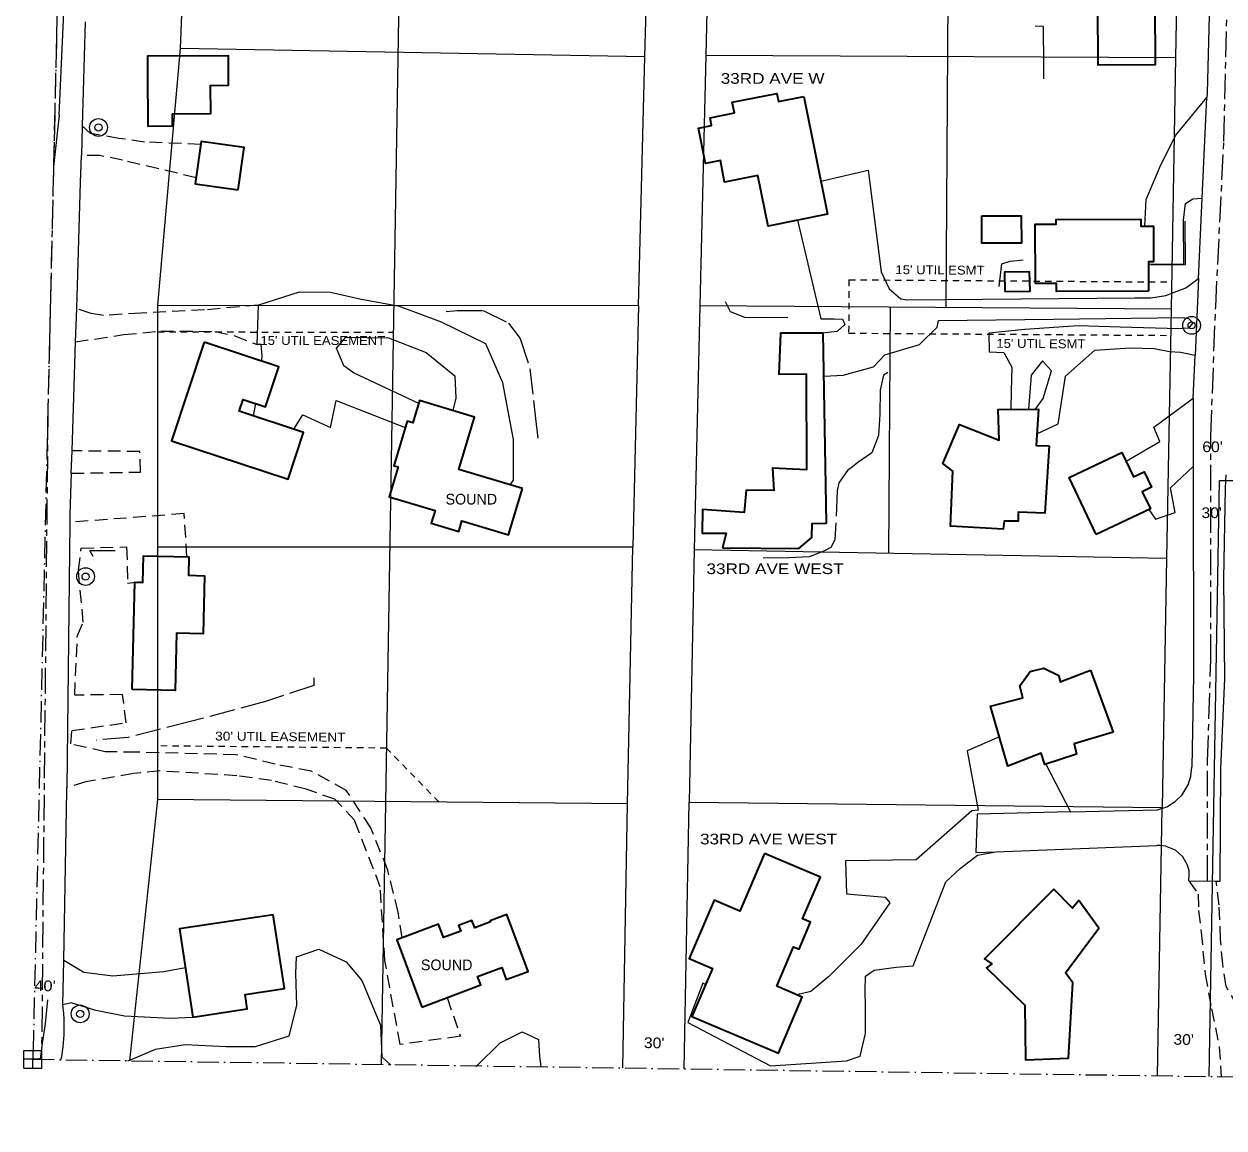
# Model space of a CAD drawing. Extents: x -861682 to -858969, y -1797841 to -1795153.
# Drawn here: x -861682 to -861008, y -1797836 to -1797216 of the extents above; entities that cross this region are included whole.
import ezdxf

# ---------------------------------------------------------------- set-up
doc = ezdxf.new("R2010")
doc.units = 0
doc.header["$LTSCALE"] = 2.4
for name, pattern in [('DOT_DASHED', [7.7, 5, -1.2, 0.3, -1.2]), ('LONG_DASH_SHORT_DASH', [9.9, 6, -1.2, 1.5, -1.2]), ('LONG_DASHED', [7.5, 6, -1.5]), ('MEDIUM_DASHED', [4.5, 3, -1.5]), ('SHORT_DASHED', [2.7, 1.5, -1.2])]:
    doc.linetypes.add(name, pattern=pattern)
for name, color, linetype, lineweight in [('10', 7, 'Continuous', 25), ('11', 7, 'Continuous', 13), ('12', 7, 'Continuous', 35), ('14', 7, 'Continuous', 25), ('18', 7, 'Continuous', 13), ('30', 7, 'Continuous', 13), ('31', 7, 'Continuous', 13), ('32', 7, 'LONG_DASH_SHORT_DASH', 13), ('42', 7, 'Continuous', 25), ('46', 7, 'Continuous', 13), ('47', 7, 'SHORT_DASHED', 13), ('52', 7, 'LONG_DASHED', 13), ('54', 7, 'Continuous', 13), ('61', 7, 'Continuous', 13)]:
    doc.layers.add(name, color=color, linetype=linetype, lineweight=lineweight)
doc.layers.add('43', color=7, linetype='Continuous')

msp = doc.modelspace()

# ---------------------------------------------------------------- linework, layer by layer
at = {"layer": '10'}
for p, q in [((-861647.407, -1797214.598), (-861649.011, -1797273.028)), ((-861019.853, -1797313.609), (-861017.272, -1797257.025)), ((-861649.011, -1797273.028), (-861649.47, -1797289.752)), ((-861021.917, -1797358.836), (-861019.853, -1797313.609)), ((-861021.917, -1797358.836), (-861023.882, -1797401.894)), ((-861024.977, -1797425.893), (-861023.882, -1797401.894)), ((-861024.977, -1797425.893), (-861024.938, -1797464.393)), ((-861655.169, -1797468.153), (-861654.723, -1797455.579)), ((-861656.037, -1797495.755), (-861657.707, -1797644.754)), ((-861093.92, -1797658.395), (-861045.067, -1797657.174)), ((-861135.81, -1797680.763), (-861045.459, -1797677.249)), ((-861027.43, -1797697.014), (-861012.076, -1797697.157)), ((-861659.839, -1797766.63), (-861659.402, -1797741.788))]:
    msp.add_line(p, q, dxfattribs=at)
for points in [[(-861015.76, -1797203.66), (-861017.164, -1797254.647), (-861017.272, -1797257.025)], [(-861652.099, -1797375.675), (-861649.886, -1797304.898), (-861649.47, -1797289.752)], [(-861654.723, -1797455.579), (-861653.654, -1797425.356), (-861652.684, -1797394.362), (-861652.099, -1797375.675)], [(-861024.938, -1797464.393), (-861024.823, -1797581.757), (-861025.797, -1797633.244)], [(-861655.169, -1797468.153), (-861655.987, -1797491.254), (-861656.037, -1797495.755)], [(-861012.076, -1797697.157), (-861009.718, -1797697.179), (-861009.5, -1797633.887), (-861007.105, -1797583.339), (-861007.802, -1797527.372), (-861006.825, -1797476.594), (-861006.515, -1797469.019)], [(-861045.067, -1797657.174), (-861039.847, -1797655.447), (-861035.151, -1797652.587), (-861031.221, -1797648.742), (-861027.798, -1797643.108), (-861026.266, -1797638.213), (-861025.841, -1797634.937), (-861025.797, -1797633.244)], [(-861659.402, -1797741.788), (-861657.726, -1797646.418), (-861657.707, -1797644.754)], [(-861093.92, -1797658.395), (-861146.371, -1797659.706), (-861146.994, -1797681.199), (-861135.81, -1797680.763)], [(-861027.43, -1797697.014), (-861027.137, -1797693.726), (-861027.304, -1797691.53), (-861028.091, -1797688.324), (-861030.741, -1797683.522), (-861034.803, -1797679.835), (-861040.484, -1797677.515), (-861043.767, -1797677.172), (-861045.459, -1797677.249)], [(-861660.946, -1797797.525), (-861660.54, -1797795.669), (-861659.753, -1797790.216), (-861659.211, -1797783.628), (-861659.093, -1797779.222), (-861659.094, -1797778.12), (-861659.172, -1797774.815), (-861659.352, -1797771.606), (-861659.839, -1797766.63)]]:
    msp.add_lwpolyline(points, dxfattribs=at)
at = {"layer": '11'}
for p, q in [((-861550.805, -1797395.896), (-861549.949, -1797373.692)), ((-861551.74, -1797428.996), (-861552.921, -1797435.919)), ((-861107.715, -1797631.519), (-861093.92, -1797658.395))]:
    msp.add_line(p, q, dxfattribs=at)
for points in [[(-861052.021, -1797329.413), (-861051.404, -1797314.296), (-861043.216, -1797294.898), (-861034.781, -1797278.334), (-861017.272, -1797257.025)], [(-861234.103, -1797304.022), (-861207.574, -1797297.92), (-861200.26, -1797355.041), (-861195.735, -1797364.47), (-861189.1, -1797370.111), (-861185.791, -1797370.806), (-861057.794, -1797369.583), (-861048.82, -1797369.547), (-861040.323, -1797368.332), (-861029.005, -1797364.036), (-861021.917, -1797358.836)], [(-861050.072, -1797350.658), (-861030.239, -1797350.58), (-861030.338, -1797326.02), (-861029.196, -1797316.569), (-861025.191, -1797313.955), (-861019.853, -1797313.609)], [(-861247.232, -1797325.95), (-861234.163, -1797381.392), (-861226.606, -1797381.362), (-861221.881, -1797381.579), (-861220.688, -1797384.645), (-861224.924, -1797388.44), (-861233.405, -1797389.416)], [(-861408.546, -1797474.711), (-861406.676, -1797472.07), (-861406.767, -1797449.162), (-861412.799, -1797417.305), (-861422.333, -1797395.38), (-861447.179, -1797383.198), (-861470.83, -1797374.555), (-861493.046, -1797370.393), (-861509.592, -1797366.681), (-861527.069, -1797366.514), (-861549.949, -1797373.692)], [(-861232.292, -1797413.694), (-861221.519, -1797412.988), (-861204.534, -1797408.432), (-861198.185, -1797401.557), (-861178.606, -1797395.811), (-861168.726, -1797386.089), (-861168.033, -1797382.307), (-861103.326, -1797381.574), (-861030.591, -1797380.573), (-861027.518, -1797381.269), (-861025.147, -1797383.621), (-861027.497, -1797386.701), (-861032.927, -1797386.959), (-861065.994, -1797386.147), (-861089.614, -1797385.298), (-861119.598, -1797387.307), (-861139.663, -1797389.513), (-861139.622, -1797399.904), (-861131.354, -1797400.344), (-861126.834, -1797408.591), (-861127.254, -1797421.818), (-861127.337, -1797432.208)], [(-861459.978, -1797428.941), (-861496.659, -1797411.736), (-861502.107, -1797407.744), (-861506.161, -1797397.841), (-861500.991, -1797391.68), (-861476.9, -1797392.056), (-861455.849, -1797400.237), (-861439.737, -1797413.398), (-861439.215, -1797425.912), (-861440.747, -1797432.94)], [(-861548.133, -1797405.261), (-861547.945, -1797402.259), (-861548.442, -1797395.885), (-861550.805, -1797395.896)], [(-861112.775, -1797446.049), (-861100.729, -1797440.369), (-861096.585, -1797413.665), (-861080.113, -1797398.957), (-861060.279, -1797397.696), (-861046.816, -1797398.114), (-861038.308, -1797399.733), (-861032.166, -1797400.181), (-861023.882, -1797401.894)], [(-861113.564, -1797432.153), (-861109.287, -1797426.233), (-861104.627, -1797410.628), (-861109.609, -1797404.98), (-861115.953, -1797413.035), (-861117.386, -1797432.168)], [(-861530.196, -1797443.392), (-861525.141, -1797435.231), (-861509.525, -1797442.489), (-861506.279, -1797427.362), (-861467.509, -1797442.49)], [(-861062.691, -1797461.316), (-861043.773, -1797450.293), (-861047.111, -1797442.277), (-861024.977, -1797425.893)], [(-861049.855, -1797488.55), (-861046.195, -1797493.993), (-861035.111, -1797490.17), (-861037.764, -1797476.247), (-861024.938, -1797464.393)], [(-861133.806, -1797616.207), (-861151.946, -1797624.068), (-861145.673, -1797657.342), (-861149.213, -1797657.828), (-861180.512, -1797685.348), (-861220.186, -1797685.743), (-861219.639, -1797704.398), (-861197.905, -1797706.2), (-861195.294, -1797709.496), (-861211.496, -1797732.705), (-861229.608, -1797750.726), (-861239.729, -1797759.268), (-861247.679, -1797761.044)], [(-861298.827, -1797755.228), (-861300.442, -1797754.552), (-861308.856, -1797776.549), (-861262.47, -1797800.924), (-861219.735, -1797798.154), (-861211.952, -1797795.526), (-861208.933, -1797782.761), (-861208.995, -1797767.41), (-861209.265, -1797758.91), (-861209.062, -1797750.643), (-861204.116, -1797747.317), (-861191.842, -1797745.615), (-861182.163, -1797744.867), (-861163.932, -1797697.562), (-861155.932, -1797690.209), (-861146.043, -1797682.612), (-861135.81, -1797680.763)], [(-861591.03, -1797745.96), (-861603.235, -1797748.22), (-861631.801, -1797750.696), (-861648.105, -1797748.636), (-861659.402, -1797741.788)], [(-861586.784, -1797773.884), (-861599.588, -1797774.419), (-861625.335, -1797773.105), (-861641.407, -1797769.863), (-861655.121, -1797765.667), (-861659.839, -1797766.63)]]:
    msp.add_lwpolyline(points, dxfattribs=at)
at = {"layer": '11', "linetype": 'MEDIUM_DASHED'}
for points in [[(-861582.445, -1797283.493), (-861614.08, -1797282.082), (-861628.339, -1797280.061), (-861644.329, -1797277.245), (-861649.011, -1797273.028)], [(-861585.041, -1797302.194), (-861626.32, -1797292.287), (-861639.083, -1797289.74), (-861649.47, -1797289.752)], [(-861549.949, -1797373.692), (-861580.403, -1797376.412), (-861615.821, -1797378.208), (-861637.07, -1797379.474), (-861643.923, -1797378.32), (-861652.099, -1797375.675)], [(-861652.684, -1797394.362), (-861625.691, -1797390.292), (-861604.917, -1797388.319), (-861574.451, -1797388.433), (-861563.341, -1797390.987), (-861550.805, -1797395.896)], [(-861655.169, -1797468.153), (-861616.171, -1797467.479), (-861616.69, -1797455.909), (-861654.723, -1797455.579)], [(-861590.157, -1797515.049), (-861591.753, -1797490.76), (-861656.037, -1797495.755)], [(-861469.362, -1797729.004), (-861471.589, -1797714.627), (-861477.352, -1797691.035), (-861486.895, -1797667.221), (-861500.677, -1797646.259), (-861520.322, -1797635.474), (-861540.648, -1797631.542), (-861562.633, -1797626.198), (-861618.61, -1797624.77), (-861636.087, -1797624.605), (-861655.47, -1797620.196), (-861654.792, -1797612.636), (-861624.344, -1797608.263), (-861626.297, -1797592.448), (-861653.218, -1797592.792), (-861651.7, -1797559.251), (-861648.424, -1797551.681), (-861651.138, -1797522.644), (-861649.535, -1797510.121), (-861624.032, -1797509.547), (-861623.478, -1797529.854), (-861614.948, -1797528.693)], [(-861444.026, -1797762.632), (-861436.592, -1797784.388), (-861470.345, -1797789.01), (-861479.037, -1797741.815), (-861481.566, -1797700.499), (-861495.886, -1797663.244), (-861507.034, -1797651.245), (-861523.115, -1797645.641), (-861542.736, -1797640.76), (-861562.113, -1797638.004), (-861605.342, -1797635.344), (-861620.215, -1797636.821), (-861646.883, -1797641.415), (-861657.707, -1797644.754)], [(-861027.43, -1797697.014), (-861022.205, -1797704.55), (-861021.932, -1797713.759), (-861020.467, -1797725.798), (-861018.247, -1797749.405), (-861014.626, -1797768.992), (-861010.29, -1797790.229), (-861009.146, -1797807.296)], [(-860793.836, -1797741.71), (-860796.661, -1797765.758), (-860796.654, -1797767.411), (-860810.281, -1797785.178), (-860824.892, -1797792.794), (-860842.836, -1797793.81), (-860860.091, -1797790.1), (-860902.834, -1797790.507), (-860938.496, -1797790.178), (-860966.606, -1797788.637), (-860988.843, -1797779.28), (-860999.752, -1797767.752), (-861006.41, -1797756.442), (-861008.35, -1797743.934), (-861009.588, -1797729.769), (-861010.373, -1797710.643), (-861012.076, -1797697.157)]]:
    msp.add_lwpolyline(points, dxfattribs=at)
at = {"layer": '12'}
for points in [[(-861078.528, -1797205.062), (-861046.411, -1797204.933), (-861046.275, -1797238.704), (-861078.392, -1797238.834)], [(-861612.348, -1797242.635), (-861612.226, -1797273.099), (-861598.292, -1797273.043), (-861598.32, -1797266.195), (-861576.829, -1797266.107), (-861576.894, -1797250.286), (-861566.738, -1797250.244), (-861566.806, -1797233.714), (-861612.384, -1797233.902)], [(-861243.636, -1797256.499), (-861230.383, -1797322.571), (-861263.762, -1797329.266), (-861269.47, -1797300.809), (-861288.134, -1797304.553), (-861290.55, -1797292.511), (-861298.907, -1797294.188), (-861302.894, -1797274.319), (-861295.468, -1797272.829), (-861296.33, -1797268.533), (-861282.629, -1797265.784), (-861283.832, -1797259.789), (-861258.786, -1797254.763), (-861257.864, -1797259.356)], [(-861561.307, -1797309.029), (-861557.983, -1797285.077), (-861582.199, -1797281.717), (-861585.523, -1797305.669)], [(-861143.706, -1797323.641), (-861121.508, -1797323.552), (-861121.446, -1797338.902), (-861143.644, -1797338.992)], [(-861050.016, -1797365.773), (-861101.735, -1797365.98), (-861101.753, -1797361.493), (-861113.561, -1797361.54), (-861113.694, -1797328.242), (-861101.886, -1797328.195), (-861101.896, -1797325.597), (-861054.429, -1797325.414), (-861054.414, -1797329.422), (-861047.328, -1797329.395), (-861047.252, -1797349.467), (-861050.076, -1797349.477)], [(-861130.783, -1797366.097), (-861116.614, -1797365.804), (-861116.839, -1797354.941), (-861131.008, -1797355.235)], [(-861289.38, -1797510.083), (-861246.396, -1797510.383), (-861239.1, -1797504.213), (-861238.896, -1797496.42), (-861230.867, -1797496.152), (-861232.712, -1797389.414), (-861256.801, -1797389.511), (-861257.653, -1797412.422), (-861242.303, -1797412.361), (-861242.087, -1797466.205), (-861261.22, -1797465.337), (-861260.461, -1797477.85), (-861276.049, -1797477.677), (-861277.18, -1797490.198), (-861300.568, -1797488.403), (-861300.75, -1797501.865), (-861287.288, -1797501.81)], [(-861580.565, -1797394.595), (-861598.764, -1797449.931), (-861533.356, -1797471.443), (-861524.723, -1797445.193), (-861560.832, -1797433.318), (-861558.662, -1797426.72), (-861545.964, -1797430.896), (-861538.568, -1797408.407)], [(-861401.695, -1797476.769), (-861437.399, -1797466.049), (-861428.557, -1797436.601), (-861459.489, -1797427.313), (-861463.226, -1797439.76), (-861466.403, -1797438.806), (-861473.941, -1797463.908), (-861471.601, -1797464.611), (-861476.634, -1797481.364), (-861450.773, -1797489.133), (-861452.901, -1797496.216), (-861437.536, -1797500.832), (-861435.745, -1797494.872), (-861409.505, -1797502.758)], [(-861105.874, -1797452.667), (-861108.32, -1797490.463), (-861123.2, -1797490.051), (-861123.18, -1797495.01), (-861131.21, -1797495.042), (-861131.664, -1797499.531), (-861161.192, -1797497.761), (-861159.898, -1797467.055), (-861165.584, -1797462.59), (-861156.225, -1797440.826), (-861133.991, -1797449.475), (-861134.532, -1797432.237), (-861111.861, -1797432.146), (-861113.196, -1797452.461)], [(-861079.459, -1797502.626), (-861094.702, -1797470.569), (-861065.006, -1797456.449), (-861058.491, -1797470.151), (-861052.451, -1797467.279), (-861048.3, -1797476.008), (-861053.545, -1797478.502), (-861048.968, -1797488.128)], [(-861620.876, -1797589.591), (-861619.464, -1797529.364), (-861614.967, -1797529.469), (-861614.617, -1797514.478), (-861589.095, -1797515.074), (-861589.337, -1797525.45), (-861580.289, -1797525.661), (-861581.049, -1797558.247), (-861595.965, -1797557.899), (-861596.717, -1797590.154)], [(-861082.695, -1797578.682), (-861069.85, -1797613.614), (-861091.74, -1797620.046), (-861090.535, -1797625.946), (-861108.224, -1797631.684), (-861110.375, -1797625.317), (-861129.003, -1797632.712), (-861138.82, -1797598.98), (-861120.654, -1797594.183), (-861122.334, -1797587.577), (-861116.462, -1797579.524), (-861108.913, -1797577.605), (-861100.394, -1797581.821), (-861099.672, -1797585.362)], [(-861265.781, -1797681.673), (-861279.584, -1797714.083), (-861294.106, -1797707.898), (-861308.091, -1797740.733), (-861295.024, -1797746.298), (-861306.495, -1797773.233), (-861257.946, -1797793.909), (-861244.522, -1797762.389), (-861258.844, -1797756.29), (-861249.39, -1797734.089), (-861246.316, -1797735.398), (-861239.9, -1797720.33), (-861244.318, -1797718.449), (-861234.357, -1797695.052)], [(-861103.218, -1797701.802), (-861142.265, -1797740.925), (-861138.003, -1797743.744), (-861141.065, -1797745.881), (-861119.49, -1797766.812), (-861119.131, -1797797.513), (-861095.045, -1797796.708), (-861092.617, -1797754.425), (-861096.654, -1797748.773), (-861077.862, -1797723.664), (-861089.26, -1797708.123), (-861092.785, -1797712.388)], [(-861541.724, -1797716.089), (-861594.356, -1797724.093), (-861586.824, -1797773.62), (-861556.33, -1797768.983), (-861557.551, -1797760.955), (-861535.413, -1797757.588)], [(-861458.148, -1797767.942), (-861425.135, -1797755.529), (-861426.916, -1797750.792), (-861413.37, -1797745.699), (-861410.797, -1797752.543), (-861398.434, -1797747.895), (-861410.436, -1797715.971), (-861419.857, -1797719.513), (-861419.619, -1797720.147), (-861428.496, -1797723.479), (-861430.068, -1797719.291), (-861437.585, -1797722.113), (-861436.399, -1797725.273), (-861446.114, -1797728.919), (-861448.957, -1797721.345), (-861472.343, -1797730.123)]]:
    msp.add_lwpolyline(points, close=True, dxfattribs=at)
at = {"layer": '14'}
for points in [[(-861108.829, -1797246.515), (-861108.86, -1797238.721), (-861108.946, -1797217.231), (-861113.67, -1797217.014)], [(-861029.627, -1797326.554), (-861029.528, -1797351.114), (-861048.657, -1797351.19)], [(-861642.904, -1797514.817), (-861644.806, -1797511.519), (-861630.4, -1797511.461)]]:
    msp.add_lwpolyline(points, dxfattribs=at)
at = {"layer": '18'}
for points in [[(-861623.4, -1797798.074), (-861620.985, -1797797.173), (-861607.782, -1797791.688), (-861591.261, -1797789.024), (-861568.113, -1797790.112), (-861551.582, -1797790.046), (-861532.713, -1797784.066), (-861528.53, -1797767.046), (-861529.074, -1797749.099), (-861528.64, -1797739.651), (-861516.14, -1797735.35), (-861500.761, -1797742.61), (-861491.981, -1797752.966), (-861481.489, -1797778.193), (-861480.709, -1797795.902), (-861475.591, -1797800.538)], [(-861427.836, -1797801.23), (-861427.552, -1797801.121), (-861414.143, -1797788.078), (-861401.887, -1797781.889), (-861392.66, -1797786.103), (-861392.15, -1797795.547), (-861391.47, -1797801.757)]]:
    msp.add_lwpolyline(points, dxfattribs=at)
at = {"layer": '30'}
for p, q in [((-861163.628, -1797374.823), (-861160.072, -1796802.305)), ((-861465.508, -1796850.044), (-861480.985, -1797800.155)), ((-861332.881, -1797234.296), (-861593.747, -1797229.638)), ((-861034.85, -1797234.814), (-861298.67, -1797233.588)), ((-861606.511, -1797373.754), (-861336.579, -1797373.985)), ((-861302.157, -1797373.847), (-861037.376, -1797375.712)), ((-861195.88, -1797513.194), (-861195.019, -1797374.602)), ((-861606.53, -1797509.436), (-861339.74, -1797509.472)), ((-861039.875, -1797516.041), (-861305.282, -1797511.198)), ((-861342.634, -1797653.874), (-861606.549, -1797651.29)), ((-861308.13, -1797652.868), (-861042.331, -1797655.814))]:
    msp.add_line(p, q, dxfattribs=at)
at = {"layer": '31'}
for centre, radius in [((-861639.855, -1797273.92), 5), ((-861639.855, -1797273.92), 2), ((-861025.85, -1797385.041), 5), ((-861025.85, -1797385.041), 2), ((-861647.109, -1797526.17), 5), ((-861647.109, -1797526.17), 2), ((-861650.137, -1797771.787), 5), ((-861650.137, -1797771.787), 2)]:
    msp.add_circle(centre, radius, dxfattribs=at)
at = {"layer": '32'}
for points in [[(-861016.908, -1797697.112), (-861016.908, -1797629.868), (-861015.071, -1797572.938), (-861015.071, -1797447.139), (-861012.317, -1797374.599), (-861007.726, -1797281.857), (-861003.087, -1797084.148), (-860992.207, -1796696.344), (-860992.984, -1796576.661), (-860989.487, -1796449.983), (-860987.933, -1796343.901), (-860987.544, -1796199.737), (-860984.047, -1796080.831), (-860987.933, -1795887.705), (-860991.735, -1795769.455)], [(-861635.972, -1796031.868), (-861668.34, -1797434.932), (-861671.877, -1797797.365)]]:
    msp.add_lwpolyline(points, dxfattribs=at)
at = {"layer": '42'}
for p, q in [((-861593.747, -1797229.638), (-861588.243, -1797084.303)), ((-861332.881, -1797234.296), (-861329.456, -1797088.773)), ((-861295.45, -1797089.904), (-861298.67, -1797233.588)), ((-861662.023, -1797266.955), (-861655.483, -1797122.019)), ((-861336.579, -1797373.985), (-861332.881, -1797234.296)), ((-861298.67, -1797233.588), (-861302.157, -1797373.847)), ((-861665.13, -1797295.772), (-861665.13, -1797295.773)), ((-861665.13, -1797295.773), (-861665.13, -1797295.775)), ((-861336.579, -1797373.985), (-861339.74, -1797509.472)), ((-861302.157, -1797373.847), (-861305.282, -1797511.198)), ((-861342.634, -1797653.874), (-861339.74, -1797509.472)), ((-861305.282, -1797511.198), (-861308.13, -1797652.868)), ((-861622.2, -1797798.091), (-861606.549, -1797651.29)), ((-861345.345, -1797802.137), (-861342.634, -1797653.874)), ((-861310.845, -1797802.641), (-861308.13, -1797652.868)), ((-861044.944, -1797806.526), (-861042.331, -1797655.814))]:
    msp.add_line(p, q, dxfattribs=at)
for points in [[(-861032.296, -1797091.766), (-861034.85, -1797234.814), (-861037.376, -1797375.712)], [(-861606.549, -1797651.29), (-861606.511, -1797373.754), (-861593.747, -1797229.638)], [(-861662.023, -1797266.955), (-861665.129, -1797295.77), (-861665.13, -1797295.772)], [(-861037.376, -1797375.712), (-861039.875, -1797516.041), (-861042.331, -1797655.814)], [(-861015.939, -1797806.95), (-861010.094, -1797472.113), (-860981.052, -1797472.221)]]:
    msp.add_lwpolyline(points, dxfattribs=at)
at = {"layer": '47'}
for p, q in [((-861218.295, -1797359.437), (-861037.107, -1797360.713)), ((-861606.513, -1797388.754), (-861474.285, -1797388.867))]:
    msp.add_line(p, q, dxfattribs=at)
for points in [[(-861218.295, -1797359.437), (-861218.481, -1797389.437), (-861037.643, -1797390.711)], [(-861448.58, -1797652.837), (-861478.092, -1797622.546), (-861606.545, -1797621.288)]]:
    msp.add_lwpolyline(points, dxfattribs=at)
at = {"layer": '52'}
for points in [[(-861133.865, -1797363.276), (-861132.499, -1797350.519), (-861127.782, -1797349.083), (-861120.464, -1797348.345)], [(-861287.81, -1797371.688), (-861284.954, -1797377.345), (-861276.912, -1797380.383), (-861266.992, -1797380.579), (-861252.587, -1797380.521)], [(-861444.604, -1797377.282), (-861438.466, -1797376.785), (-861423.824, -1797376.726), (-861409.625, -1797383.754), (-861402.978, -1797392.465), (-861397.478, -1797409.446), (-861394.296, -1797437.301), (-861393.071, -1797448.396)], [(-861196.492, -1797411.469), (-861198.847, -1797413.132), (-861200.703, -1797421.405), (-861200.885, -1797434.867), (-861201.781, -1797446.915), (-861205.521, -1797456.613), (-861213.293, -1797462.075), (-861216.359, -1797464.58), (-861219.125, -1797466.505), (-861223.937, -1797473.601), (-861224.899, -1797477.932), (-861226.222, -1797505.598), (-861228.451, -1797509.841), (-861231.751, -1797511.507), (-861240.475, -1797515.085), (-861252.045, -1797515.604), (-861269.048, -1797515.909)], [(-861518.88, -1797583.042), (-861518.863, -1797587.293), (-861545.985, -1797596.376), (-861587.506, -1797607.406), (-861623.13, -1797616.523), (-861641.073, -1797618.012)]]:
    msp.add_lwpolyline(points, dxfattribs=at)
at = {"layer": '54'}
msp.add_lwpolyline([(-861668.59, -1797763.832), (-861669.716, -1797777.297), (-861671.562, -1797788.168), (-861672.673, -1797797.354)], dxfattribs=at)
at = {"layer": '61', "linetype": 'DOT_DASHED'}
msp.add_line((-861615.801, -1795157.51), (-861676.699, -1797797.295), dxfattribs=at)
at = {"layer": '61'}
for p, q in [((-861681.699, -1797792.295), (-861671.699, -1797792.295)), ((-861681.699, -1797802.295), (-861681.699, -1797792.295)), ((-861676.699, -1797792.295), (-861676.699, -1797797.295)), ((-861671.699, -1797802.295), (-861671.699, -1797792.295)), ((-861671.699, -1797797.295), (-861681.699, -1797797.295)), ((-861681.699, -1797802.295), (-861671.699, -1797802.295)), ((-861676.699, -1797802.295), (-861676.699, -1797797.295))]:
    msp.add_line(p, q, dxfattribs=at)
at = {"layer": '61', "linetype": 'DOT_DASHED'}
msp.add_lwpolyline([(-861676.699, -1797797.295), (-859488.961, -1797829.261), (-859035.9, -1797835.881)], dxfattribs=at)

# ---------------------------------------------------------------- texts
at = {"layer": '43', "width": 1.1}
for s, p in [("60'", (-861019.833, -1797456.283)), ("30'", (-861020.305, -1797493.312))]:
    msp.add_text(s, height=6, dxfattribs=at).set_placement(p)
at = {"layer": '43'}
for s, rotation, width, p in [("40'", 358.665, 1.15, (-861676, -1797758.873)), ("30'", 358.955, 1.1, (-861333.549, -1797790.966)), ("30'", 359.005, 1.1, (-861036.107, -1797789.076))]:
    msp.add_text(s, height=6, rotation=rotation, dxfattribs=dict(at, width=width)).set_placement(p)
at = {"layer": '46', "width": 1.2}
for s, p in [('33RD AVE W', (-861290.349, -1797249.393)), ('33RD AVE WEST', (-861298.352, -1797524.774)), ('33RD AVE WEST', (-861301.979, -1797676.594))]:
    msp.add_text(s, height=6, dxfattribs=at).set_placement(p)
at = {"layer": '46'}
for p in [(-861444.927, -1797485.697), (-861458.756, -1797747.258)]:
    msp.add_text('SOUND', height=6, dxfattribs=at).set_placement(p)
at = {"layer": '47'}
for s, rotation, width, p in [("15' UTIL ESMT", 359.596, 1.1, (-861192.194, -1797356.287)), ("15' UTIL EASEMENT", 359.942, 1.1, (-861548.874, -1797396.041)), ("15' UTIL ESMT", 359.596, 1.1, (-861135.526, -1797397.664)), ("30' UTIL EASEMENT", 359.458, 1.15, (-861574.361, -1797618.231))]:
    msp.add_text(s, height=5, rotation=rotation, dxfattribs=dict(at, width=width)).set_placement(p)

doc.saveas('drawing.dxf')
